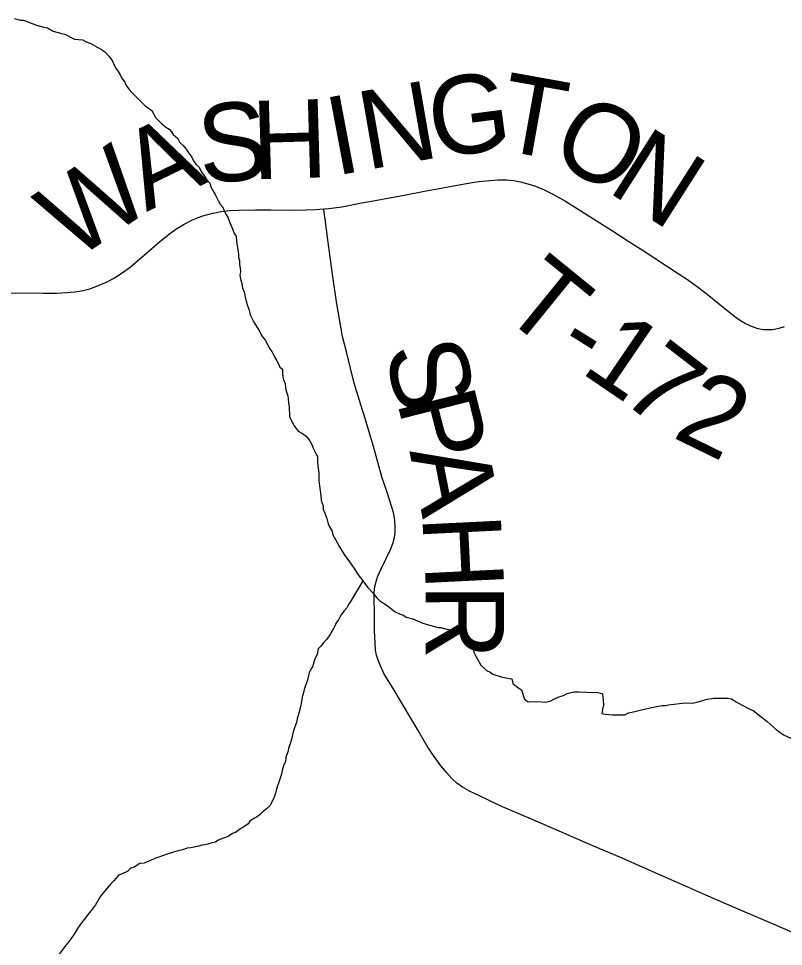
# Model space of a CAD drawing. Extents: x 1410790 to 1770854, y 448063 to 770588.
# Drawn here: x 1535374 to 1538300, y 599435 to 602986 of the extents above; entities that cross this region are included whole.
import ezdxf

# ---------------------------------------------------------------- set-up
doc = ezdxf.new("R2010")
doc.units = 0
for name, color, linetype in [('GM_X_Minor_River', 7, 'Continuous'), ('GM_X_Township_Road', 7, 'Continuous'), ('GM_X_Township_Road_Text', 7, 'Continuous')]:
    doc.layers.add(name, color=color, linetype=linetype)

msp = doc.modelspace()

# ---------------------------------------------------------------- linework, layer by layer
at = {"layer": 'GM_X_Minor_River'}
for points in [[(1535358.2, 602985.5), (1535380.2, 602979.3), (1535392.2, 602979.2), (1535442.1, 602960.6), (1535470.1, 602952.3), (1535484.1, 602950.1), (1535506, 602937.9), (1535534, 602929.6), (1535550, 602925.4), (1535587.8, 602907), (1535617.9, 602904.6), (1535631.8, 602896.5), (1535649.8, 602890.3), (1535691.6, 602865.8), (1535703.6, 602857.6), (1535719.4, 602841.4), (1535731.3, 602825.3), (1535741.2, 602805.1), (1535747.1, 602793), (1535755, 602782.9), (1535762.9, 602770.8), (1535766.8, 602758.7), (1535780.6, 602742.5), (1535784.6, 602732.5), (1535796.4, 602714.3), (1535806.3, 602702.2), (1535820.2, 602690), (1535857.9, 602651.5), (1535869.9, 602643.4), (1535883.8, 602633.2), (1535897.6, 602607), (1535919.4, 602584.7), (1535937.3, 602570.5), (1535949.3, 602562.3), (1535959.2, 602552.2), (1535965.1, 602542.1), (1535983, 602525.9), (1535990.9, 602511.8), (1536002.8, 602499.6)], [(1536002.8, 602499.6), (1536014.7, 602485.4), (1536020.6, 602475.4), (1536036.4, 602455.2), (1536042.3, 602441), (1536052.2, 602428.9), (1536064.1, 602416.8), (1536072, 602400.6), (1536081.9, 602386.5), (1536093.7, 602368.3), (1536105.7, 602356.2), (1536109.5, 602342.1), (1536117.4, 602328), (1536125.3, 602311.8), (1536137.1, 602289.7), (1536145, 602275.6), (1536154.9, 602263.4), (1536160.8, 602249.3), (1536166.7, 602237.2), (1536174.6, 602225.1), (1536180.4, 602207), (1536192.2, 602180.8), (1536198.1, 602162.7), (1536206, 602152.6), (1536207.8, 602132.5), (1536215.4, 602084.3), (1536215.3, 602072.3), (1536219.2, 602058.2), (1536219, 602044.2), (1536220.9, 602030.1), (1536222.8, 602018.1), (1536220.7, 602002), (1536224.5, 601984), (1536228.4, 601971.9), (1536230.2, 601953.8), (1536236.1, 601939.7), (1536240, 601919.6), (1536243.8, 601903.5), (1536249.7, 601887.4), (1536255.5, 601869.3), (1536259.4, 601851.3), (1536265.3, 601841.2), (1536273.1, 601823), (1536287, 601802.8), (1536294.9, 601788.7), (1536302.7, 601772.6), (1536316.6, 601754.4), (1536326.5, 601738.3), (1536334.3, 601722.1), (1536342.3, 601712), (1536348.2, 601701.9), (1536354.1, 601687.8), (1536361.9, 601675.7), (1536369.8, 601661.6), (1536373.7, 601651.5), (1536383.7, 601643.4), (1536383.5, 601623.4), (1536387.3, 601603.3), (1536393.2, 601589.2), (1536395.1, 601571.1), (1536398.9, 601557), (1536402.8, 601545), (1536404.7, 601532.9), (1536406.6, 601512.8), (1536408.5, 601500.8), (1536410.1, 601462.7), (1536419.9, 601440.5), (1536427.8, 601426.4), (1536443.7, 601406.2), (1536459.6, 601398), (1536473.5, 601387.8), (1536485.4, 601373.7), (1536495.3, 601355.5), (1536501.2, 601341.4), (1536511, 601321.3), (1536516.9, 601309.2), (1536516.7, 601291.1), (1536518.6, 601273.1), (1536522.4, 601246.9), (1536522.1, 601216.9), (1536529.6, 601160.6), (1536531.4, 601140.6), (1536539.2, 601120.4), (1536539.1, 601108.4), (1536545, 601092.3), (1536552.8, 601072.2), (1536558.7, 601052.1), (1536564.6, 601037.9), (1536572.5, 601025.8), (1536576.3, 601009.8), (1536586.2, 600991.6), (1536601.9, 600963.4), (1536619.7, 600935.1), (1536639.5, 600906.8), (1536657.3, 600880.6), (1536673.1, 600856.4), (1536690.9, 600834.1), (1536708.7, 600809.9), (1536728.5, 600787.6), (1536742.4, 600769.4), (1536756.3, 600757.2)], [(1536690.9, 600834.1), (1536646.2, 600758.4), (1536638.1, 600746.4), (1536629.9, 600730.5), (1536619.8, 600718.5), (1536609.7, 600706.6), (1536603.6, 600696.7), (1536597.5, 600684.7), (1536589.3, 600672.7), (1536583.2, 600660.8), (1536566.9, 600630.8), (1536552.7, 600610.9), (1536538.6, 600595), (1536530.5, 600583.1), (1536520.4, 600573.2), (1536516.2, 600553.2), (1536506, 600531.2), (1536497.7, 600505.2), (1536491.6, 600495.2), (1536485.5, 600481.3), (1536483.4, 600471.3), (1536479.2, 600453.3), (1536471, 600433.3), (1536466.9, 600417.3), (1536462.8, 600401.3), (1536458.6, 600389.3), (1536456.5, 600371.3), (1536452.3, 600351.3), (1536446.1, 600327.3), (1536439.9, 600307.3), (1536437.8, 600295.3), (1536433.6, 600281.3), (1536427.5, 600267.3), (1536423.4, 600251.3), (1536419.2, 600231.3), (1536413, 600209.3), (1536406.8, 600193.3), (1536404.7, 600183.3), (1536400.6, 600171.3), (1536396.5, 600159.3), (1536394.3, 600141.3), (1536388.2, 600129.3), (1536384.1, 600117.3), (1536382, 600107.3), (1536379.9, 600093.3), (1536373.7, 600075.3), (1536369.6, 600063.4), (1536363.5, 600045.4), (1536359.3, 600031.4), (1536357.2, 600021.4), (1536353.1, 600009.4), (1536349, 599999.4), (1536342.9, 599987.4), (1536336.8, 599973.4), (1536320.6, 599959.6), (1536308.5, 599949.7), (1536298.4, 599939.8), (1536284.3, 599929.9), (1536274.3, 599924), (1536258.1, 599914.1), (1536252.1, 599904.1), (1536235.9, 599892.3), (1536223.9, 599886.4), (1536203.7, 599870.5), (1536191.6, 599866.7), (1536175.5, 599854.8), (1536157.4, 599848.9), (1536137.3, 599841.1), (1536127.2, 599833.2), (1536109.2, 599829.4), (1536097.1, 599825.5), (1536085.1, 599823.6), (1536075.1, 599821.7), (1536063, 599817.8), (1536045, 599814), (1536032.9, 599812.1), (1536018.9, 599810.3), (1536000.8, 599804.4), (1535984.8, 599800.6), (1535966.7, 599794.8), (1535938.6, 599787), (1535914.5, 599777.2), (1535894.4, 599771.4), (1535878.3, 599763.6), (1535854.2, 599753.8), (1535838.1, 599752), (1535816, 599738.2), (1535801.9, 599734.3), (1535791.8, 599722.4), (1535767.7, 599710.6), (1535755.6, 599706.7), (1535739.4, 599686.8), (1535727.3, 599674.9), (1535696.9, 599639.1), (1535686.8, 599627.2), (1535668.5, 599593.3), (1535652.3, 599573.4), (1535640.1, 599557.5), (1535630, 599543.5), (1535617.9, 599529.6), (1535607.7, 599515.7)], [(1536756.3, 600757.2), (1536766.3, 600751.1), (1536784.2, 600738.9), (1536796.1, 600728.8), (1536814, 600714.5), (1536834, 600706.3), (1536844, 600704.2), (1536855.9, 600694.1), (1536881.9, 600687.8), (1536901.8, 600679.5), (1536919.8, 600671.3), (1536977.7, 600654.7), (1536989.7, 600654.6), (1537011.7, 600648.3), (1537025.7, 600646.2), (1537041.7, 600642), (1537051.7, 600637.9), (1537071.6, 600629.7), (1537081.6, 600625.6), (1537097.4, 600603.3), (1537107.4, 600595.2), (1537115.1, 600561), (1537124.9, 600542.9), (1537142.6, 600510.6), (1537164.5, 600490.4), (1537178.5, 600484.2), (1537188.4, 600476.1), (1537220.3, 600465.7), (1537250.3, 600459.4), (1537260.3, 600459.3), (1537264.2, 600441.2), (1537284.1, 600425), (1537298, 600416.8), (1537309.7, 600380.6), (1537323.6, 600370.4), (1537361.7, 600372), (1537387.7, 600369.8), (1537407.8, 600373.6), (1537421.9, 600381.4), (1537440, 600389.3), (1537458, 600395.1), (1537472.1, 600403), (1537488.2, 600406.8), (1537500.2, 600408.7), (1537518.2, 600408.5), (1537548.3, 600408.2), (1537590.3, 600405.8), (1537608.3, 600401.6), (1537610.1, 600375.5), (1537611.9, 600357.4), (1537607.8, 600341.4), (1537605.6, 600325.4), (1537617.6, 600323.3), (1537645.6, 600321), (1537673.7, 600320.7), (1537693.7, 600320.5), (1537707.8, 600328.4), (1537731.9, 600334.1), (1537762, 600341.8), (1537790.1, 600347.6), (1537816.2, 600353.3), (1537836.2, 600357.1), (1537850.2, 600357), (1537860.3, 600358.9), (1537892.3, 600362.6), (1537922.4, 600366.3), (1537950.4, 600366), (1537970.5, 600369.8), (1537990.6, 600375.6), (1538008.7, 600381.4), (1538032.7, 600385.2), (1538066.8, 600384.8), (1538086.8, 600384.6), (1538100.8, 600382.5), (1538118.7, 600370.3), (1538142.6, 600358), (1538166.6, 600345.7), (1538184.5, 600337.5), (1538202.4, 600323.3), (1538238.2, 600294.9), (1538272, 600264.4), (1538299.8, 600244.1), (1538327.8, 600231.8)], [(1535607.7, 599515.7), (1535599.6, 599503.8), (1535589.5, 599487.8), (1535583.4, 599477.8), (1535571.2, 599459.9), (1535563.1, 599450), (1535555, 599440), (1535540.8, 599420.1), (1535532.7, 599410.2), (1535524.6, 599400.2), (1535514.5, 599388.3), (1535508.4, 599378.3), (1535505.8, 599374.2)]]:
    msp.add_lwpolyline(points, dxfattribs=at)
at = {"layer": 'GM_X_Township_Road'}
for points in [[(1536541.1, 602257.4), (1536560.2, 602258.8), (1536610.8, 602265.3), (1536685.2, 602280.3), (1536723.6, 602286.8), (1536807.1, 602302.4), (1536842.3, 602308.7), (1536926.1, 602324.4), (1537079.1, 602352.7), (1537132.8, 602361.5), (1537162.1, 602365), (1537205.4, 602368.3), (1537241.8, 602368), (1537268.3, 602365.8), (1537294.2, 602360.7), (1537322.2, 602353.4), (1537350.9, 602343.9), (1537384.6, 602330.1), (1537420.1, 602312.6), (1537465.8, 602286.6), (1537549.2, 602234.5), (1537645.7, 602172.9), (1537708.8, 602132.4), (1537763.8, 602097.3), (1537897.6, 602010.1), (1537933, 601986.6), (1537980.7, 601951.9), (1538014.6, 601925.9), (1538082.8, 601869.3), (1538118.6, 601841.1), (1538142.8, 601824.8), (1538159.7, 601815.5), (1538180.1, 601806.5), (1538201.5, 601799.8), (1538223.5, 601796), (1538239.3, 601795.1), (1538258.4, 601795.8), (1538283.4, 601800.4), (1538304.4, 601807.4)], [(1536124.7, 602242.2), (1536148.3, 602247), (1536181.9, 602250.6), (1536215.3, 602252.7), (1536279.9, 602253.3), (1536339.3, 602253), (1536413.2, 602251.9), (1536472.2, 602253), (1536509.7, 602255.2), (1536541.1, 602257.4)], [(1538441, 599442.5), (1538272.9, 599514.5), (1538135.9, 599573.2), (1538003.5, 599630.5), (1537934.6, 599661.2), (1537817.8, 599712.6), (1537673.7, 599776), (1537571.3, 599820.1), (1537441.7, 599875.3), (1537345.6, 599917.3), (1537225.6, 599968.7), (1537186.8, 599986.3), (1537163.6, 599998.3), (1537098.5, 600029.4), (1537072.6, 600044.5), (1537050.9, 600060), (1537031.4, 600077.8), (1537011.8, 600098.7), (1536989.6, 600125.4), (1536957.1, 600170.9), (1536937.2, 600201.1), (1536902.5, 600260.4), (1536811.1, 600415.8), (1536771.1, 600478.7), (1536758.6, 600508.9), (1536749.4, 600530.1), (1536743.4, 600549), (1536739.6, 600568.5), (1536737.4, 600594.6), (1536736.3, 600620.4), (1536735.1, 600640.7), (1536735.7, 600712.6), (1536734, 600763.2), (1536734, 600788), (1536736.8, 600811.6), (1536741.3, 600831.2), (1536748.6, 600851.5), (1536761.5, 600879.4), (1536797.5, 600956.5), (1536806.7, 600980.6), (1536811.5, 600999.1), (1536814.1, 601018), (1536814.7, 601040.4), (1536812.7, 601066), (1536807.8, 601094.6), (1536801, 601119.5), (1536783.2, 601172.2), (1536763.6, 601231.2), (1536733.5, 601339), (1536699.2, 601455.3), (1536683.4, 601507.6), (1536658.1, 601589.7), (1536627.8, 601710.6), (1536613.1, 601768.5), (1536603, 601827), (1536589.5, 601901.2), (1536576, 601997.9), (1536557.3, 602139.1), (1536546.8, 602217.7), (1536543.1, 602243.2), (1536541.1, 602257.4)], [(1535253.1, 601935.7), (1535469.5, 601934.4), (1535518.4, 601934.4), (1535560.4, 601936.7), (1535573.2, 601937.9), (1535589, 601939.9), (1535620.8, 601945.4), (1535645.9, 601951.7), (1535673.2, 601961.1), (1535705.9, 601975.3), (1535714.6, 601979.4), (1535740, 601993), (1535770, 602012.3), (1535801.4, 602035.5), (1535836.5, 602064.7), (1535912.9, 602131.5), (1535946.1, 602158.3), (1535975.7, 602179.4), (1536006.7, 602198.5), (1536036.1, 602213.7), (1536060.2, 602224.1), (1536078.8, 602230.8), (1536117, 602240.9), (1536124.7, 602242.2)]]:
    msp.add_lwpolyline(points, dxfattribs=at)

# ---------------------------------------------------------------- texts
at = {"layer": 'GM_X_Township_Road_Text'}
for s, rotation, p in [('G', 7.4854, (1536961.5, 602450.7)), ('T', 349.8542, (1537198.9, 602485.7)), ('N', 9.8806, (1536704.7, 602405.9)), ('H', 1.6504, (1536269.5, 602370.1)), ('I', 10.6983, (1536584.7, 602383.2)), ('O', 330.317, (1537394.5, 602455.3)), ('S', 5.0477, (1536072.5, 602352.6)), ('A', 25.911, (1535862.8, 602244.9)), ('N', 327.4739, (1537620.5, 602326.6)), ('W', 34.3899, (1535586.1, 602054.4)), ('T', 320.8757, (1537209, 601863.5)), ('1', 325.7398, (1537518.4, 601634.7)), ('-', 328.0847, (1537416.6, 601698)), ('S', 284.178, (1536770.6, 601718.3)), ('7', 322.3521, (1537667.4, 601533.4)), ('2', 333.9721, (1537869.9, 601385.6)), ('P', 284.1434, (1536820.1, 601522.1)), ('A', 281.0974, (1536868.7, 601330)), ('H', 272.8206, (1536918.1, 601082.3)), ('R', 270.1034, (1536931, 600822.3))]:
    msp.add_text(s, height=300, rotation=rotation, dxfattribs=at).set_placement(p)

doc.saveas('drawing.dxf')
